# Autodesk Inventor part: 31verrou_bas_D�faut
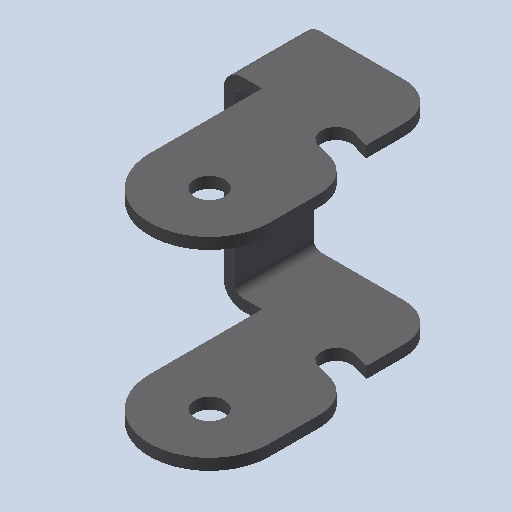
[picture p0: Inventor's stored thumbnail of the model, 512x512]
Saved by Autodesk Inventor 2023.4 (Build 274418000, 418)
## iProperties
Created: 2011-01
Part Number: 31verrou_bas_D�faut
Document SubType Name: Modeling
Designer: eric
Density: 1 g/cm^3
Mass: 14.4766 g
Surface Area: 112.976 cm^2
Volume: 14.4766 cm^3
Material: Générique
Appearance: Green
Author: eric
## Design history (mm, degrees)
feature "Base1"
node "Corps solides"
node "Corps surfaciques"
node "Solide1"
